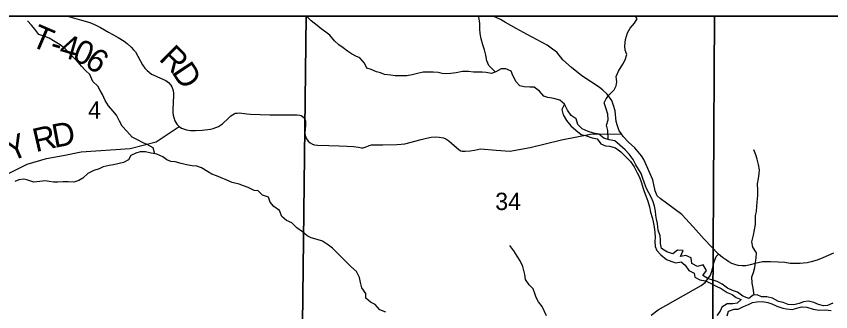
# Model space of a CAD drawing. Extents: x -3.6 to 34, y 0 to 32.8.
# Drawn here: x -0.41 to 1.556, y 32.129 to 32.843 of the extents above; entities that cross this region are included whole.
import ezdxf

# ---------------------------------------------------------------- set-up
doc = ezdxf.new("R2010")
doc.units = 0
for name, color, linetype in [('GM_X_Corporation', 7, 'Continuous'), ('GM_X_County_Road', 7, 'Continuous'), ('GM_X_Minor_River', 7, 'Continuous'), ('GM_X_Section_Text', 7, 'Continuous'), ('GM_X_Township_Road', 7, 'Continuous'), ('GM_X_Township_Road_Text', 7, 'Continuous'), ('SH_Data', 7, 'Continuous')]:
    doc.layers.add(name, color=color, linetype=linetype)

msp = doc.modelspace()

# ---------------------------------------------------------------- linework, layer by layer
at = {"layer": 'GM_X_Corporation'}
for points in [[(3.1705, 28.9337), (3.1705, 32.8429), (-3.6295, 32.8429), (-3.6295, 26.0429), (2.3706, 26.0429), (2.3712, 26.0804), (2.3716, 26.1248), (2.3732, 26.2253), (2.3789, 26.6097), (2.3911, 27.5117), (2.3952, 27.9336), (2.3997, 28.282), (2.4082, 28.9473), (2.5416, 28.945), (2.5837, 28.9442), (2.8343, 28.9397)], [(3.1705, 30.458), (3.1705, 32.8429), (-3.6295, 32.8429), (-3.6295, 30.6462), (-3.5736, 30.6453), (-2.8007, 30.6338), (-2.7027, 30.634), (-2.3541, 30.6318), (-0.5034, 30.5954), (-0.453, 30.5952), (-0.398, 30.5946), (0.2583, 30.5905), (0.2578, 30.5133), (0.3556, 30.5115), (0.4055, 30.5105), (1.2437, 30.4948), (1.7819, 30.4857), (3.0419, 30.4594)], [(0.2894, 32.8429), (-0.7278, 32.8429), (-0.7385, 32.1141), (0.2807, 32.0992)], [(1.2753, 32.8429), (0.2894, 32.8429), (0.2807, 32.0992), (0.279, 32.0211), (1.2712, 32.0083)], [(2.2831, 32.8429), (1.2753, 32.8429), (1.2712, 32.0083), (2.2789, 31.9792)]]:
    msp.add_lwpolyline(points, close=True, dxfattribs=at)
at = {"layer": 'GM_X_County_Road'}
for points in [[(1.2853, 32.268), (1.2506, 32.3038), (1.2243, 32.3338), (1.1965, 32.3633), (1.1599, 32.3912), (1.1444, 32.4025), (1.1376, 32.4086), (1.1321, 32.4205), (1.1266, 32.4478), (1.1052, 32.4963), (1.0994, 32.5057), (1.0831, 32.5246), (1.0676, 32.5383), (1.055, 32.5524), (1.0509, 32.5588), (1.0455, 32.5662), (1.0412, 32.578), (1.038, 32.5883), (1.0355, 32.6139), (1.0321, 32.6275), (1.0275, 32.6393), (1.0215, 32.648), (1.0156, 32.6553), (1.0062, 32.6642), (0.9973, 32.6715), (0.9554, 32.6992), (0.9305, 32.7191), (0.9093, 32.7379), (0.8949, 32.7559), (0.8849, 32.7632), (0.8718, 32.7731), (0.8233, 32.799), (0.7966, 32.8133), (0.7712, 32.8279), (0.7593, 32.8348), (0.7414, 32.8429)], [(1.1226, 32.1205), (1.1394, 32.133), (1.2437, 32.1917), (1.2531, 32.1991), (1.2598, 32.208), (1.2656, 32.2169), (1.2698, 32.2287), (1.2739, 32.2465), (1.28, 32.262), (1.2853, 32.268)], [(1.5629, 32.2702), (1.5368, 32.2588), (1.5234, 32.2535), (1.5094, 32.2492), (1.4994, 32.2471), (1.4907, 32.2461), (1.4826, 32.2451), (1.4698, 32.2451), (1.4581, 32.2454), (1.4456, 32.2472), (1.4294, 32.2484), (1.4107, 32.249), (1.4022, 32.2495), (1.3913, 32.2489), (1.3742, 32.2453), (1.3615, 32.2417), (1.351, 32.2398), (1.3421, 32.2394), (1.3326, 32.2402), (1.325, 32.2425), (1.3175, 32.2454), (1.3103, 32.2492), (1.3045, 32.2534), (1.2953, 32.2599), (1.2853, 32.268)]]:
    msp.add_lwpolyline(points, dxfattribs=at)
at = {"layer": 'GM_X_Minor_River'}
for points in [[(0.9138, 32.6304), (0.9026, 32.6401), (0.8877, 32.6444), (0.8732, 32.6468), (0.8633, 32.6493), (0.8529, 32.6617), (0.8402, 32.6717), (0.8295, 32.6712), (0.8159, 32.6724), (0.8059, 32.6749), (0.797, 32.6847), (0.7888, 32.6997), (0.7845, 32.7102), (0.7715, 32.7161), (0.7604, 32.7159), (0.7473, 32.7089), (0.7371, 32.7049), (0.7241, 32.707), (0.7146, 32.708), (0.7036, 32.7081), (0.6934, 32.708), (0.6816, 32.7097), (0.6672, 32.7091), (0.6516, 32.7065), (0.6388, 32.7048), (0.6285, 32.7035), (0.6179, 32.7044), (0.6083, 32.7066), (0.5966, 32.7075), (0.5863, 32.7077), (0.5723, 32.7075), (0.5586, 32.7046), (0.5454, 32.7013), (0.5329, 32.6992), (0.5234, 32.6987), (0.5139, 32.6985), (0.5044, 32.6991), (0.4938, 32.7001), (0.4786, 32.7021), (0.469, 32.7058), (0.4595, 32.7086), (0.4469, 32.7141), (0.4365, 32.7174), (0.4303, 32.7298), (0.4194, 32.7425), (0.4099, 32.7465), (0.3995, 32.7524), (0.3899, 32.7587), (0.3791, 32.7669), (0.3688, 32.7735), (0.358, 32.7832), (0.3467, 32.7971), (0.3371, 32.8041), (0.326, 32.8127), (0.3164, 32.8205), (0.3021, 32.832), (0.2902, 32.8429)], [(0.7459, 32.7083), (0.7311, 32.7238), (0.726, 32.7351), (0.7234, 32.7491), (0.7206, 32.7615), (0.7166, 32.774), (0.7125, 32.7887), (0.7096, 32.8016), (0.7091, 32.8122), (0.7089, 32.8251), (0.7072, 32.8365), (0.7061, 32.8429)], [(1.0187, 32.5447), (1.0181, 32.5665), (1.0152, 32.5794), (1.0192, 32.5927), (1.0182, 32.6064), (1.0142, 32.6188), (1.009, 32.6335), (1.0138, 32.6435), (1.0216, 32.6531), (1.0332, 32.6651), (1.0383, 32.675), (1.0397, 32.6845), (1.0383, 32.697), (1.0438, 32.71), (1.0541, 32.7272), (1.0597, 32.7372), (1.0636, 32.7502), (1.06, 32.7611), (1.0591, 32.771), (1.0607, 32.7865), (1.0658, 32.8026), (1.072, 32.814), (1.0825, 32.826), (1.0888, 32.8363), (1.0848, 32.8429)], [(-0.076, 32.5104), (-0.0793, 32.5248), (-0.0938, 32.5329), (-0.1038, 32.5365), (-0.1172, 32.5443), (-0.1302, 32.5505), (-0.143, 32.5647), (-0.1546, 32.577), (-0.1612, 32.5891), (-0.1683, 32.6034), (-0.1768, 32.6146), (-0.1876, 32.6262), (-0.1958, 32.6393), (-0.2022, 32.654), (-0.2076, 32.6638), (-0.2135, 32.6739), (-0.2255, 32.6855), (-0.2326, 32.7017), (-0.2426, 32.7114), (-0.2523, 32.7219), (-0.2604, 32.732), (-0.2736, 32.7447), (-0.2821, 32.7544), (-0.2921, 32.7641), (-0.3044, 32.7734), (-0.3201, 32.7833), (-0.3305, 32.79), (-0.3412, 32.7936), (-0.3553, 32.7991), (-0.3654, 32.8114), (-0.3732, 32.8212), (-0.3832, 32.8316)], [(0.9138, 32.6304), (0.9071, 32.6171), (0.9104, 32.6046), (0.9182, 32.5907), (0.9291, 32.578), (0.9406, 32.5675), (0.9541, 32.5567), (0.964, 32.5546), (0.9804, 32.5492), (0.9926, 32.5464), (1.0012, 32.5344), (1.0127, 32.5293), (1.0225, 32.529), (1.0366, 32.5251), (1.0497, 32.5155), (1.0613, 32.5031), (1.0725, 32.4915), (1.0815, 32.4788), (1.0893, 32.4641), (1.0944, 32.454), (1.0996, 32.44), (1.1024, 32.4287), (1.106, 32.4189), (1.1096, 32.4087), (1.1144, 32.3955), (1.1184, 32.3823), (1.1213, 32.3694), (1.1249, 32.3562), (1.1277, 32.3456), (1.1298, 32.3335), (1.1312, 32.3199), (1.1322, 32.3081), (1.1316, 32.2986), (1.1325, 32.2861), (1.1361, 32.2763), (1.1462, 32.2659), (1.1596, 32.2547), (1.1723, 32.25), (1.1826, 32.2468), (1.1951, 32.2489), (1.2047, 32.241), (1.214, 32.2279), (1.2266, 32.2221), (1.2279, 32.2122), (1.2402, 32.2056), (1.2535, 32.2035), (1.2658, 32.1977), (1.2796, 32.1907), (1.2918, 32.1844), (1.306, 32.1752), (1.3183, 32.1701), (1.3283, 32.1627), (1.3397, 32.1583), (1.33, 32.1494), (1.3202, 32.1474), (1.3065, 32.1475), (1.293, 32.1393), (1.2897, 32.1298), (1.2815, 32.1198)], [(1.5612, 32.1494), (1.5484, 32.1435), (1.5389, 32.143), (1.5267, 32.1462), (1.5156, 32.1506), (1.5027, 32.1542), (1.4902, 32.1524), (1.48, 32.1485), (1.4671, 32.1449), (1.4531, 32.1461), (1.4412, 32.1505), (1.4305, 32.1537), (1.416, 32.1611), (1.4019, 32.1646), (1.389, 32.1648), (1.379, 32.1696), (1.3688, 32.1683), (1.3587, 32.1609), (1.3441, 32.166), (1.3314, 32.176), (1.3189, 32.1796), (1.3074, 32.1858), (1.2943, 32.1951), (1.2824, 32.2017), (1.2725, 32.2046), (1.2603, 32.2078), (1.2476, 32.216), (1.2562, 32.2279), (1.2479, 32.2421), (1.2347, 32.2378), (1.2209, 32.2451), (1.2192, 32.2587), (1.2062, 32.2646), (1.1933, 32.2621), (1.2003, 32.2763), (1.1866, 32.2772), (1.175, 32.2686), (1.1609, 32.273), (1.1478, 32.2818), (1.1453, 32.2932), (1.1455, 32.3027), (1.1446, 32.3121), (1.1398, 32.3257), (1.1381, 32.3416), (1.136, 32.3526), (1.1343, 32.3624), (1.1334, 32.3719), (1.1309, 32.384), (1.1277, 32.3942), (1.1237, 32.404), (1.1174, 32.4164), (1.1112, 32.4266), (1.1068, 32.439), (1.102, 32.4533), (1.0984, 32.4631), (1.0918, 32.4729), (1.0856, 32.4838), (1.0789, 32.4962), (1.0696, 32.5097), (1.0599, 32.5198), (1.0468, 32.531), (1.0348, 32.5418), (1.0211, 32.5438), (1.0085, 32.5485), (0.9966, 32.5578), (0.9833, 32.5599), (0.9707, 32.5646), (0.9565, 32.5704), (0.9453, 32.5816), (0.9413, 32.5952), (0.9298, 32.603), (0.9208, 32.6158), (0.9138, 32.6304)], [(0.4825, 32.1278), (0.468, 32.1328), (0.4564, 32.1463), (0.4453, 32.1518), (0.4341, 32.1615), (0.4335, 32.1725), (0.4242, 32.186), (0.4206, 32.1996), (0.4185, 32.2117), (0.411, 32.2256), (0.3975, 32.2383), (0.3743, 32.2614), (0.3628, 32.2726), (0.3535, 32.2823), (0.3435, 32.2897), (0.3289, 32.2994), (0.3163, 32.3033), (0.3022, 32.3069), (0.2922, 32.312), (0.2811, 32.3221), (0.2669, 32.3313), (0.2553, 32.3433), (0.2426, 32.3492), (0.2311, 32.3588), (0.2251, 32.3735), (0.2117, 32.3828), (0.2028, 32.3936), (0.1992, 32.4053), (0.1846, 32.4104), (0.1742, 32.4209), (0.164, 32.4218), (0.1494, 32.4292), (0.1383, 32.4332), (0.128, 32.4372), (0.1112, 32.4407), (0.0979, 32.4465), (0.0833, 32.4527), (0.0734, 32.4568), (0.0623, 32.4615), (0.0512, 32.4678), (0.0374, 32.4763), (0.0259, 32.4806), (0.0149, 32.4812), (0.0012, 32.484), (-0.0118, 32.4868), (-0.0267, 32.4911), (-0.0366, 32.4917), (-0.0465, 32.4961), (-0.0561, 32.5032), (-0.071, 32.5094), (-0.0844, 32.5122), (-0.0981, 32.515), (-0.111, 32.5155), (-0.1212, 32.5116), (-0.1336, 32.5064), (-0.1395, 32.4961), (-0.1512, 32.4891), (-0.175, 32.4834), (-0.186, 32.482)], [(1.3717, 32.1686), (1.3689, 32.1857), (1.3668, 32.1974), (1.3661, 32.213), (1.3694, 32.2237), (1.3733, 32.2355), (1.3747, 32.248), (1.376, 32.2579), (1.3773, 32.2708), (1.368, 32.2844), (1.3659, 32.2976), (1.3698, 32.314), (1.3722, 32.3269), (1.3743, 32.3391), (1.3749, 32.3486), (1.3747, 32.3615), (1.3768, 32.371), (1.3781, 32.3835), (1.3787, 32.3934), (1.3799, 32.4094), (1.3801, 32.4227), (1.3798, 32.4378), (1.3815, 32.4508), (1.3836, 32.4618), (1.3842, 32.4717), (1.3821, 32.4849), (1.3784, 32.4978), (1.3756, 32.5076), (1.3709, 32.5196)], [(-0.186, 32.482), (-0.2, 32.4788), (-0.2098, 32.4737), (-0.2226, 32.47), (-0.2373, 32.463), (-0.2496, 32.4518), (-0.2594, 32.4455), (-0.2711, 32.4419), (-0.2852, 32.4428), (-0.2973, 32.4426), (-0.3098, 32.4417), (-0.3205, 32.4415), (-0.3311, 32.4432), (-0.3407, 32.4449), (-0.3535, 32.4432), (-0.3679, 32.4418), (-0.3821, 32.4465), (-0.392, 32.449), (-0.4041, 32.4477), (-0.4139, 32.4433)], [(0.8703, 32.119), (0.8593, 32.1416), (0.8504, 32.1525), (0.8449, 32.1626), (0.8421, 32.1724), (0.8381, 32.1837), (0.8284, 32.1935), (0.8195, 32.2066), (0.8174, 32.2187), (0.8125, 32.2376), (0.8066, 32.2519), (0.7992, 32.2628), (0.7914, 32.2759), (0.7813, 32.2883)], [(1.3062, 32.1183), (1.3094, 32.1301), (1.323, 32.1349), (1.3325, 32.135), (1.3457, 32.1409), (1.3578, 32.1457), (1.3676, 32.1508), (1.3782, 32.1525), (1.3914, 32.1535), (1.4044, 32.151), (1.4139, 32.1474), (1.4262, 32.1419), (1.4403, 32.1368), (1.4498, 32.1355), (1.4635, 32.1342), (1.4745, 32.1374), (1.4858, 32.1406), (1.4984, 32.1393), (1.514, 32.1346), (1.5285, 32.1322), (1.5429, 32.1332), (1.557, 32.1319)]]:
    msp.add_lwpolyline(points, dxfattribs=at)
at = {"layer": 'GM_X_Township_Road'}
for points in [[(-0.2864, 32.8429), (-0.2529, 32.8335), (-0.2328, 32.8278), (-0.221, 32.8233), (-0.2068, 32.816), (-0.1877, 32.8043), (-0.1787, 32.7992), (-0.1645, 32.7917), (-0.1494, 32.7827), (-0.142, 32.7769), (-0.1324, 32.7684), (-0.127, 32.7618), (-0.1226, 32.7565), (-0.1057, 32.7255), (-0.1001, 32.7174), (-0.0945, 32.7115), (-0.0896, 32.7074), (-0.0837, 32.7031), (-0.0492, 32.6872), (-0.0428, 32.6825), (-0.0371, 32.6764), (-0.0345, 32.6719), (-0.0322, 32.6659), (-0.0309, 32.6579), (-0.0309, 32.6517), (-0.0322, 32.6173), (-0.0322, 32.6097), (-0.0313, 32.6036), (-0.03, 32.5979), (-0.0273, 32.5899), (-0.0228, 32.5821), (-0.0165, 32.5763), (-0.0112, 32.5726), (-0.0066, 32.5704), (0.001, 32.568), (0.0102, 32.5668), (0.0224, 32.5666), (0.0387, 32.5673), (0.0586, 32.5702), (0.0652, 32.5719), (0.0715, 32.5737), (0.0784, 32.576), (0.0879, 32.5827), (0.102, 32.5965), (0.1081, 32.6024), (0.1123, 32.6048), (0.1161, 32.6068), (0.1193, 32.6082), (0.1231, 32.6089), (0.1285, 32.6092), (0.1465, 32.6069), (0.155, 32.6059), (0.2019, 32.6046), (0.2593, 32.6049), (0.2677, 32.6046), (0.2743, 32.604), (0.278, 32.6031), (0.2813, 32.6008), (0.2842, 32.5983), (0.2869, 32.5944), (0.2885, 32.5907), (0.2882, 32.5789), (0.2869, 32.5613), (0.2873, 32.5544), (0.2888, 32.5502), (0.2907, 32.5463), (0.2946, 32.5408), (0.2995, 32.5365), (0.3048, 32.5334), (0.3099, 32.532), (0.317, 32.5314), (0.3447, 32.5303), (0.3698, 32.5299), (0.389, 32.5291), (0.4039, 32.5281), (0.4158, 32.5266), (0.4236, 32.5245), (0.4275, 32.5249), (0.4347, 32.5272), (0.4416, 32.5308), (0.4473, 32.5321), (0.4558, 32.5322), (0.4747, 32.5317), (0.5083, 32.5329), (0.5188, 32.5337), (0.528, 32.5347), (0.5673, 32.5447), (0.5803, 32.5485), (0.5916, 32.5509), (0.6015, 32.5511), (0.611, 32.5506), (0.6211, 32.5491), (0.6266, 32.5469), (0.6345, 32.5414), (0.6592, 32.5202), (0.6628, 32.5175), (0.6661, 32.5164), (0.6738, 32.5165), (0.6856, 32.5174), (0.6961, 32.5191), (0.7106, 32.5222), (0.7481, 32.5195)], [(-0.2971, 32.5066), (-0.2537, 32.515), (-0.1348, 32.523), (-0.0726, 32.5392), (-0.0165, 32.5763)], [(0.7481, 32.5195), (0.7815, 32.5171), (0.8302, 32.5252), (0.9059, 32.5441), (0.9761, 32.5576), (1.0509, 32.5588)], [(-0.7414, 32.4395), (-0.7316, 32.4366), (-0.5847, 32.4281), (-0.551, 32.4291), (-0.5373, 32.431), (-0.4539, 32.4503), (-0.3835, 32.4853), (-0.3375, 32.4988), (-0.2971, 32.5066)]]:
    msp.add_lwpolyline(points, dxfattribs=at)
at = {"layer": 'SH_Data'}
msp.add_line((-3.6295, 32.8429), (3.1705, 32.8429), dxfattribs=at)

# ---------------------------------------------------------------- texts
at = {"layer": 'GM_X_Section_Text'}
for s, height, p in [('4', 0.0419, (-0.2367, 32.5956)), ('34', 0.04186, (0.7462, 32.3744))]:
    msp.add_text(s, height=height, rotation=0, dxfattribs=at).set_placement(p)
at = {"layer": 'GM_X_Township_Road_Text'}
for s, rotation, p in [('T', 336.8447, (-0.3782, 32.7726)), ('4', 344.145, (-0.3093, 32.7468)), ('0', 336.6039, (-0.2775, 32.7379)), ('-', 344.1429, (-0.3317, 32.7532)), ('6', 324.1949, (-0.2482, 32.7256)), ('R', 315.3795, (-0.0678, 32.7383)), ('D', 303.5032, (-0.0365, 32.7079)), ('D', 10.6805, (-0.3182, 32.5245)), ('R', 13.0186, (-0.3631, 32.5141)), ('Y', 23.4176, (-0.4232, 32.4901))]:
    msp.add_text(s, height=0.0568, rotation=rotation, dxfattribs=at).set_placement(p)

doc.saveas('drawing.dxf')
